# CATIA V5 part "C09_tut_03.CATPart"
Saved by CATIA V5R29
Part number: Part1
Bounding box of the stored display mesh (mm): x 0 to 224, y -87.701 to 88.93, z 0 to 67.047
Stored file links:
  C:\Users\CADCIM 00\Desktop\catia parts file\C09\C09_tut_03.CATPart
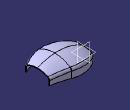
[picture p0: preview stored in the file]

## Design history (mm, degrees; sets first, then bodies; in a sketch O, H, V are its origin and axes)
Body1 (main body)
  Sketch1 on xy-plane, origin (0, 0, 0), H (1, 0, 0), V (0, 1, 0)
    arc A1 centre (95, -36.2404) radius 125 from (0, 45) to (139.6657, 80.5071) cw
    point P1 (95, -36.2404)
    point P2 (0, 45)
    arc A2 centre (289.027, 470.911) radius 418 from (139.6657, 80.5071) to (224, 58) ccw
    point P5 (224, 58)
    radius A1 = 125
    distance P2 H = 45
    distance P2 P5 H = 224
    radius A2 = 418
    distance P5 H = 58
    distance P1 V = 95
    coincidence: P2 V
    tangency: A2 A1
  Sketch2 on xy-plane, origin (0, 0, 0), H (1, 0, 0), V (0, 1, 0)
    axis line L1 (0, -58) -> (224, -58)
    point P1 (0, -58)
    point P2 (224, -58)
    arc A1 centre (112, 154.264) radius 240 from (0, -58) to (224, -58) ccw
    length L1 = 224
    radius A1 = 240
    distance H L1 = 58
    coincidence: P1 V
    horizontal: L1 H
  Sketch3 on zx-plane, origin (0, 0, 0), H (-1, 0, 0), V (0, 0, 1)
    arc A1 centre (-126.7082, -167.9142) radius 235 from (0, 30) to (-224, 46) ccw
    point P2 (0, 30)
    point P3 (-224, 46)
    axis line L1 (-224, 46) -> (-224, 0)
    point P4 (-224, 0)
    radius A1 = 235
    distance P2 H = 30
    length L1 = 46
    distance P2 P3 H = 224
    coincidence: P2 V, P4 H
    vertical: L1 V
  Sketch4 on yz-plane, origin (0, 0, 0), H (0, 1, 0), V (0, 0, 1)
    point P1 (45, 0)
    line L1 (45, 0) -> (45, 18.5632)
    point P3 (-58, 0)
    line L2 (-58, 0) -> (-58, 18.5632)
    arc A1 centre (-6.5, -89.8238) radius 120 from (-58, 18.5632) to (45, 18.5632) cw
    point P6 (0, 30)
    line L3 (45, 0) -> (-58, 0)
    reference projected point E1 (-58, 0) from Sketch2.P1
    reference projected point E2 (45, 0) from Sketch1.P2
    reference projected point E3 (0, 30) from Sketch3.P2
    construction line L4 (-58, 18.5632) -> (45, 18.5632)
    radius A1 = 120
    coincidence: P1 H, P3 H, A1 P6, P6 V, P3 E1, P1 E2, P6 E3
    vertical: L1 V, L2 V
    horizontal: L3 H, L4 H
  Plane1: type 3Points, Element1 Sketch2.P2, Element2 Sketch3.P3, Element3 Sketch1.P5
  Sketch5 on Plane1, origin (224, 0, 0), H (0, -1, 0), V (0, 0, 1)
    point P1 (-58, 0)
    line L1 (-58, 0) -> (58, 0)
    point P2 (58, 0)
    line L2 (58, 0) -> (58, 29.9794)
    arc A1 centre (0, -67) radius 113 from (58, 29.9794) to (-58, 29.9794) ccw
    point P5 (0, 46)
    line L3 (-58, 29.9794) -> (-58, 0)
    reference projected point E1 (-58, 0) from Sketch1.P5
    reference projected point E2 (58, 0) from Sketch2.P2
    reference projected point E3 (0, 46) from Sketch3.P3
    axis line L4 (58, 29.9794) -> (-58, 29.9794)
    radius A1 = 113
    coincidence: P1 H, A1 P5, P5 V, P1 E1, P2 E2, P5 E3
    horizontal: L1 H, L4 H
    vertical: L2 V, L3 V
  Loft1: solid, Sections (Sketch4; Sketch5), Guides (Sketch1; Sketch3; Sketch2)
  Fillet1: radius 25, on edge [face of Loft1 | face of Loft1] (x2)
  Fillet2: radius 15, on edge [face of Loft1 | face of Loft1]
  Shell1: ExtOffset 0, Face (face of Loft1; face of Loft1), IntOffset 3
